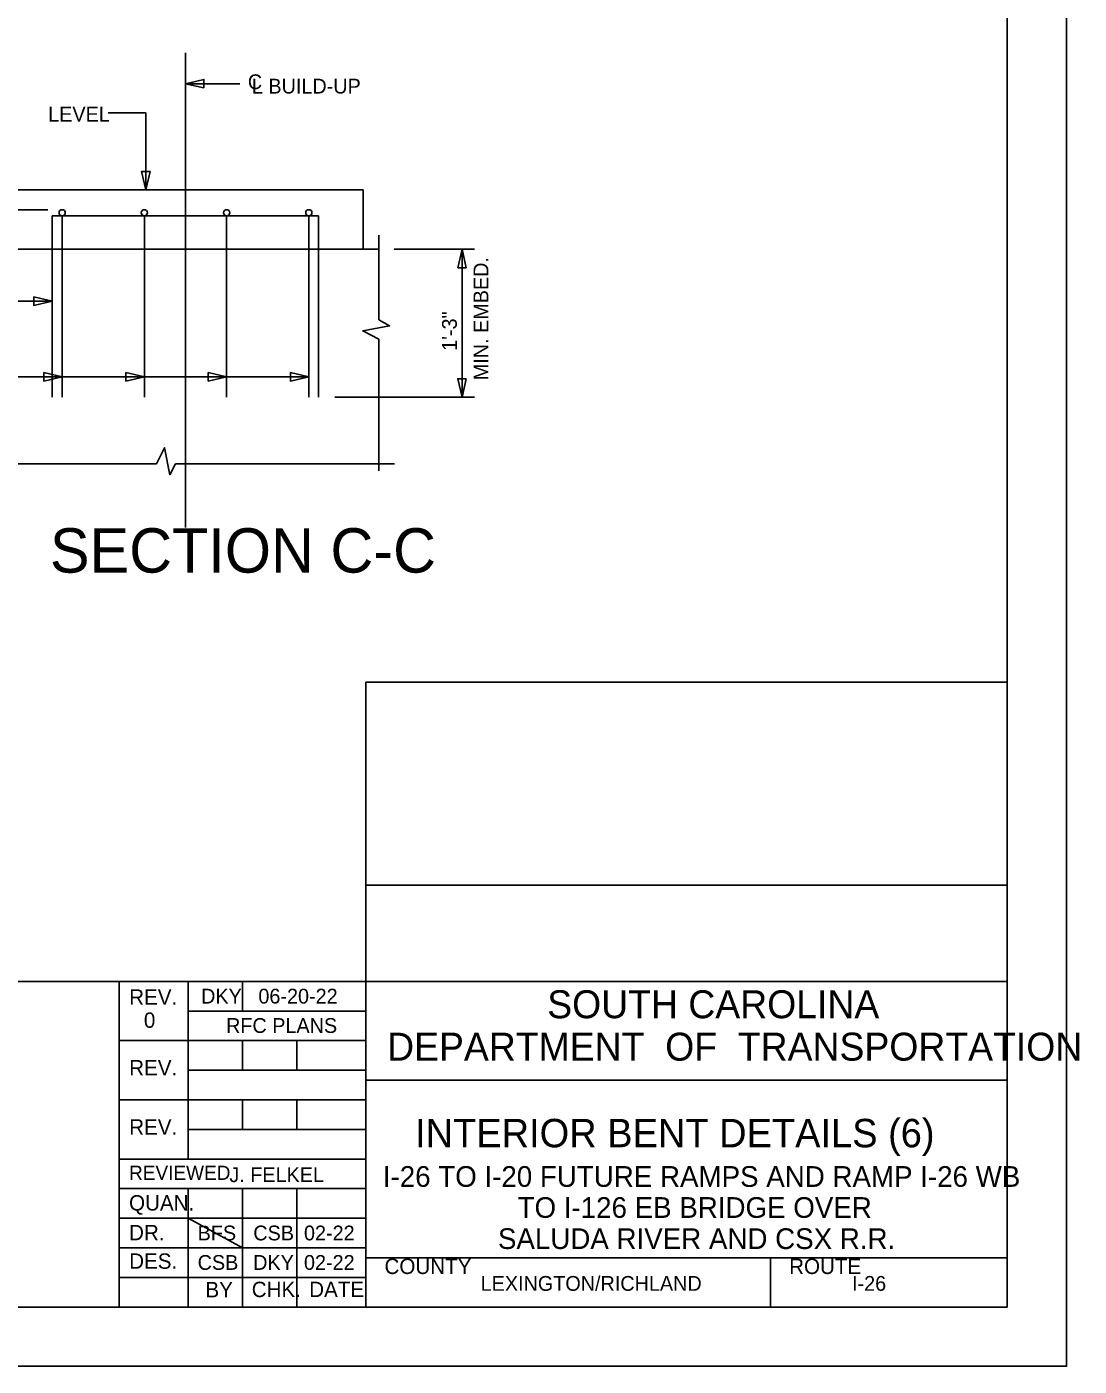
# Model space of a CAD drawing. Extents: x -133.1 to -97, y -110.1 to -88.1.
# Drawn here: x -105.92 to -97.03, y -110.1 to -98.79 of the extents above; entities that cross this region are included whole.
import ezdxf

# ---------------------------------------------------------------- set-up
doc = ezdxf.new("R2010")
doc.units = 0
for name, color, linetype in [('BR_AUTO DIMENSION', 7, 'Continuous'), ('BR_BORDER LINES', 7, 'Continuous'), ('BR_CENTER LINES', 7, 'Continuous'), ('BR_CONCRETE', 7, 'Continuous'), ('BR_REBAR', 7, 'Continuous'), ('BR_TEXT', 7, 'Continuous'), ('Default', 7, 'Continuous'), ('Level 31', 7, 'Continuous')]:
    doc.layers.add(name, color=color, linetype=linetype)

msp = doc.modelspace()

# ---------------------------------------------------------------- linework, layer by layer
at = {"layer": 'BR_AUTO DIMENSION'}
for p, q in [((-104.582, -99.272), (-104.122, -99.272)), ((-105.234, -99.519), (-104.917, -99.519)), ((-104.917, -99.519), (-104.917, -100.169)), ((-105.745, -100.336), (-106.732, -100.336)), ((-102.819, -100.67), (-102.14, -100.67)), ((-102.246, -100.67), (-102.246, -101.92)), ((-105.707, -101.109), (-106.338, -101.109)), ((-103.54, -101.748), (-106.283, -101.748)), ((-105.623, -101.748), (-105.703, -101.748)), ((-104.929, -101.748), (-105.009, -101.748)), ((-104.234, -101.748), (-104.314, -101.748)), ((-103.54, -101.748), (-103.62, -101.748)), ((-103.32, -101.92), (-102.14, -101.92))]:
    msp.add_line(p, q, dxfattribs=at)
for points in [[(-104.426, -99.308), (-104.582, -99.272), (-104.426, -99.236)], [(-104.881, -100.013), (-104.917, -100.169), (-104.953, -100.013)], [(-102.282, -100.826), (-102.246, -100.67), (-102.21, -100.826)], [(-105.863, -101.073), (-105.707, -101.109), (-105.863, -101.145)], [(-105.779, -101.712), (-105.623, -101.748), (-105.779, -101.784)], [(-105.085, -101.712), (-104.929, -101.748), (-105.085, -101.784)], [(-104.39, -101.712), (-104.234, -101.748), (-104.39, -101.784)], [(-103.696, -101.712), (-103.54, -101.748), (-103.696, -101.784)], [(-102.21, -101.764), (-102.246, -101.92), (-102.282, -101.764)]]:
    msp.add_lwpolyline(points, close=True, dxfattribs=at)
at = {"layer": 'BR_BORDER LINES'}
for p, q in [((-97.642, -109.603), (-97.642, -88.603)), ((-103.058, -109.603), (-103.058, -104.326)), ((-103.058, -104.326), (-97.642, -104.326)), ((-103.058, -106.041), (-97.642, -106.041)), ((-110.507, -106.853), (-105.142, -106.853)), ((-105.142, -109.603), (-105.142, -106.853)), ((-105.142, -106.853), (-97.642, -106.853)), ((-104.559, -106.853), (-104.559, -108.353)), ((-104.1, -107.103), (-104.1, -106.853)), ((-104.559, -107.103), (-103.058, -107.103)), ((-105.142, -107.353), (-103.058, -107.353)), ((-104.1, -107.603), (-104.1, -107.353)), ((-103.642, -107.603), (-103.642, -107.353)), ((-104.559, -107.603), (-103.058, -107.603)), ((-103.058, -107.686), (-103.058, -107.686)), ((-103.058, -107.686), (-97.641, -107.686)), ((-105.142, -107.853), (-103.058, -107.853)), ((-104.1, -108.103), (-104.1, -107.853)), ((-103.642, -108.103), (-103.642, -107.853)), ((-104.559, -108.103), (-103.058, -108.103)), ((-105.142, -108.353), (-103.058, -108.353)), ((-105.142, -108.603), (-103.058, -108.603)), ((-104.559, -108.603), (-104.559, -109.603)), ((-104.1, -108.603), (-104.1, -109.603)), ((-103.642, -108.603), (-103.642, -109.603)), ((-105.142, -108.853), (-103.058, -108.853)), ((-105.142, -109.103), (-103.058, -109.103)), ((-103.058, -109.186), (-97.642, -109.186)), ((-102.961, -109.186), (-97.642, -109.186)), ((-99.642, -109.603), (-99.642, -109.186)), ((-105.142, -109.353), (-103.058, -109.353)), ((-131.308, -109.603), (-97.642, -109.603))]:
    msp.add_line(p, q, dxfattribs=at)
at = {"layer": 'BR_CENTER LINES'}
msp.add_line((-104.582, -99.011), (-104.582, -103.02), dxfattribs=at)
at = {"layer": 'BR_CONCRETE'}
for p, q in [((-106.082, -100.169), (-103.082, -100.169)), ((-103.082, -100.169), (-103.082, -100.67)), ((-106.143, -100.67), (-102.949, -100.67))]:
    msp.add_line(p, q, dxfattribs=at)
at = {"layer": 'BR_REBAR'}
for p, q in [((-105.707, -100.388), (-105.707, -101.92)), ((-103.457, -100.388), (-105.707, -100.388)), ((-105.623, -101.92), (-105.623, -100.388)), ((-104.929, -101.92), (-104.929, -100.388)), ((-104.234, -101.92), (-104.234, -100.388)), ((-103.54, -101.92), (-103.54, -100.388)), ((-103.457, -100.388), (-103.457, -101.92))]:
    msp.add_line(p, q, dxfattribs=at)
for centre in [(-105.623, -100.362), (-104.929, -100.362), (-104.234, -100.362), (-103.54, -100.362)]:
    msp.add_circle(centre, 0.0261, dxfattribs=at)
at = {"layer": 'Default'}
for p, q in [((-102.949, -101.267), (-102.949, -100.55)), ((-102.949, -102.541), (-102.949, -101.429)), ((-106.204, -102.482), (-104.827, -102.482)), ((-104.666, -102.482), (-102.816, -102.482))]:
    msp.add_line(p, q, dxfattribs=at)
for points in [[(-102.949, -101.267), (-102.858, -101.317), (-103.084, -101.359), (-102.949, -101.429)], [(-104.666, -102.482), (-104.715, -102.574), (-104.758, -102.347), (-104.827, -102.482)]]:
    msp.add_lwpolyline(points, dxfattribs=at)
at = {"layer": 'Level 31'}
for p, q in [((-100.35, -108.126), (-100.35, -108.126)), ((-104.559, -108.853), (-104.1, -109.103))]:
    msp.add_line(p, q, dxfattribs=at)
msp.add_lwpolyline([(-133.141, -110.103), (-97.141, -110.103), (-97.141, -88.103), (-133.141, -88.103)], close=True, dxfattribs=at)

# ---------------------------------------------------------------- texts
at = {"layer": 'BR_AUTO DIMENSION'}
for s, p in [('C', (-104.055, -99.318)), ('L BUILD-UP', (-104.021, -99.355))]:
    msp.add_text(s, height=0.125, dxfattribs=at).set_placement(p)
for s, rotation, p in [('LEVEL', 360, (-105.741, -99.592)), ('MIN. EMBED.', 90, (-102.024, -101.776)), ('1\'-3" ', 90, (-102.29, -101.528))]:
    msp.add_text(s, height=0.125, rotation=rotation, dxfattribs=at).set_placement(p)
at = {"layer": 'BR_TEXT'}
msp.add_text('SECTION C-C', height=0.375, rotation=360, dxfattribs=at).set_placement((-105.726, -103.401))
for s, height, p in [('REV.', 0.13, (-105.057, -107.05)), ('DKY', 0.125, (-104.45, -107.04)), ('06-20-22', 0.125, (-103.966, -107.04)), ('SOUTH CAROLINA', 0.23587, (-101.527, -107.164)), ('0', 0.13, (-104.933, -107.245)), ('RFC PLANS', 0.125, (-104.239, -107.288)), ('DEPARTMENT  OF  TRANSPORTATION', 0.23587, (-102.879, -107.522)), ('REV.', 0.13, (-105.057, -107.647)), ('REV.', 0.13, (-105.057, -108.147)), ('INTERIOR BENT DETAILS (6)', 0.24, (-102.643, -108.254)), ('REVIEWED', 0.12, (-105.058, -108.529)), ('J. FELKEL', 0.125, (-104.211, -108.548)), ('I-26 TO I-20 FUTURE RAMPS AND RAMP I-26 WB', 0.175, (-102.915, -108.588)), ('QUAN.', 0.13, (-105.058, -108.788)), ('TO I-126 EB BRIDGE OVER', 0.175, (-101.777, -108.85)), ('DR.', 0.13, (-105.058, -109.039)), ('BFS', 0.125, (-104.479, -109.04)), ('CSB', 0.125, (-104.009, -109.04)), ('02-22', 0.125, (-103.581, -109.04)), ('SALUDA RIVER AND CSX R.R.', 0.175, (-101.943, -109.113)), ('DES.', 0.13, (-105.057, -109.28)), ('CSB', 0.125, (-104.479, -109.289)), ('DKY', 0.125, (-104.01, -109.289)), ('02-22', 0.125, (-103.581, -109.289)), ('COUNTY', 0.13, (-102.901, -109.324)), ('ROUTE', 0.13, (-99.484, -109.324)), ('LEXINGTON/RICHLAND', 0.12499, (-102.089, -109.466)), ('I-26', 0.125, (-98.953, -109.466)), ('BY', 0.13, (-104.413, -109.521)), ('CHK.', 0.13, (-104.022, -109.519)), ('DATE', 0.13, (-103.537, -109.519))]:
    msp.add_text(s, height=height, dxfattribs=at).set_placement(p)

doc.saveas('drawing.dxf')
